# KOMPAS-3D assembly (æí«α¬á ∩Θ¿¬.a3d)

Referenced files in D:\МОДЕЛЬ ТАНКА Т90\ДЕТАЛИ\БАШНЯ\башня сварная\: ящик.m3d, труба.m3d
Referenced files in D:\МОДЕЛЬ ТАНКА Т90\ДЕТАЛИ\ОБЩИЕ ДЕТАЛИ\: замки ящиков.m3d, болт м1.m3d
